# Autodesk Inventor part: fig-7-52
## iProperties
Shininess: 77.0
Length Units: 11269
Angle Units: 11279
Time Units: 11290
Mass Units: 11283
Length Display Precision: 3
Angle Display Precision: 2
Created: 2002-01
Part Number: fig-7-52
Document SubType Name: Modeling
Designer: ***
Density: 0.0
Volumn: 0.0
Area: 0.0
PropertySet Name: Model Information
Control State: 0
Master: False
Checked Out: False
Author: ***
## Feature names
1. Extrusion2
2. FaceDraft7
